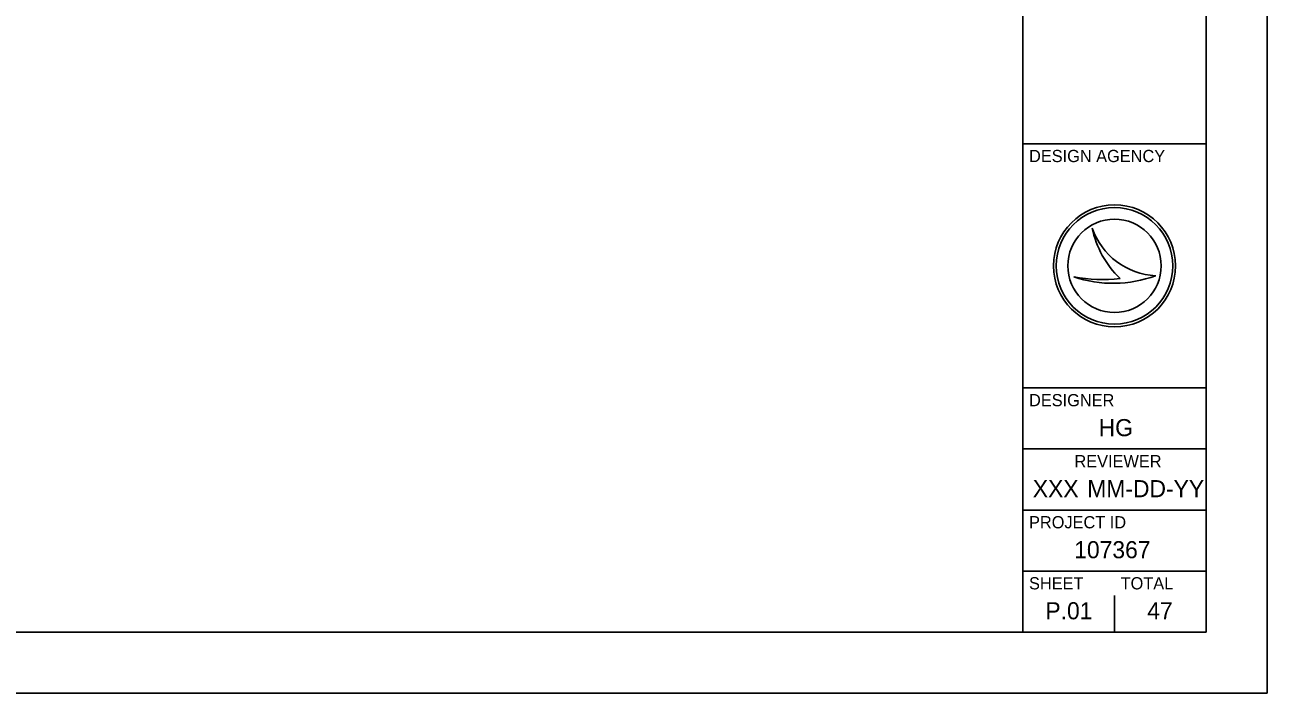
# Model space of a CAD drawing. Extents: x 0 to 34, y 0 to 22.
# Drawn here: x 23.83 to 34, y 0 to 5.47 of the extents above; entities that cross this region are included whole.
import ezdxf

# ---------------------------------------------------------------- set-up
doc = ezdxf.new("R2010")
doc.units = 0
for name, color, linetype in [('SH_Border', 7, 'Continuous'), ('SH_Cut_Line', 7, 'Continuous'), ('SH_Data', 7, 'Continuous')]:
    doc.layers.add(name, color=color, linetype=linetype)

msp = doc.modelspace()

# ---------------------------------------------------------------- linework, layer by layer
at = {"layer": 'SH_Border'}
for p, q in [((32, 0.5), (32, 21.5)), ((32, 4.5), (33.5, 4.5)), ((32, 2.5), (33.5, 2.5)), ((32, 2), (33.5, 2)), ((32, 1.5), (33.5, 1.5)), ((32, 1), (33.5, 1))]:
    msp.add_line(p, q, dxfattribs=at)
msp.add_lwpolyline([(1.5, 21.5), (33.5, 21.5), (33.5, 0.5), (1.5, 0.5)], close=True, dxfattribs=at)
at = {"layer": 'SH_Cut_Line'}
msp.add_lwpolyline([(0, 0), (34, 0), (34, 22), (0, 22)], close=True, dxfattribs=at)
at = {"layer": 'SH_Data'}
for p, q in [((32.567, 3.81), (32.567, 3.81)), ((32.75, 3.5), (32.75, 3.5)), ((32.417, 3.41), (32.417, 3.41)), ((33.087, 3.419), (33.087, 3.419)), ((32.75, 0.5), (32.75, 0.8)), ((32.375, 0.675), (32.375, 0.675))]:
    msp.add_line(p, q, dxfattribs=at)
for radius in [0.5, 0.477, 0.477, 0.382]:
    msp.add_circle((32.75, 3.5), radius, dxfattribs=at)
for centre, radius, start, end in [((33.116, 3.998), 0.58, 198.9257, 198.9319), ((33.347, 3.97), 0.796, 191.6379, 191.6421), ((33.116, 3.998), 0.58, 198.9319, 267.1657), ((33.347, 3.97), 0.796, 191.6421, 226.0947), ((32.739, 4.37), 1.013, 251.4576, 290.0832), ((32.648, 4.654), 1.266, 259.4964, 259.4995), ((32.739, 4.37), 1.013, 251.4527, 251.4576), ((32.648, 4.654), 1.266, 259.4995, 276.6672)]:
    msp.add_arc(centre, radius, start, end, dxfattribs=at)

# ---------------------------------------------------------------- texts
for s, height, p in [('DESIGN AGENCY', 0.1, (32.05, 4.35)), ('DESIGNER', 0.1, (32.05, 2.35)), ('HG', 0.14, (32.62, 2.105)), ('REVIEWER', 0.1, (32.422, 1.85)), ('XXX', 0.14, (32.081, 1.605)), ('MM-DD-YY', 0.14, (32.527, 1.605)), ('PROJECT ID', 0.1, (32.05, 1.35)), ('107367', 0.14, (32.42, 1.105)), ('SHEET', 0.1, (32.05, 0.85)), ('TOTAL', 0.1, (32.8, 0.85)), ('P.01', 0.14, (32.184, 0.605)), ('47', 0.14, (33.018, 0.605))]:
    msp.add_text(s, height=height, dxfattribs=at).set_placement(p)

doc.saveas('drawing.dxf')
